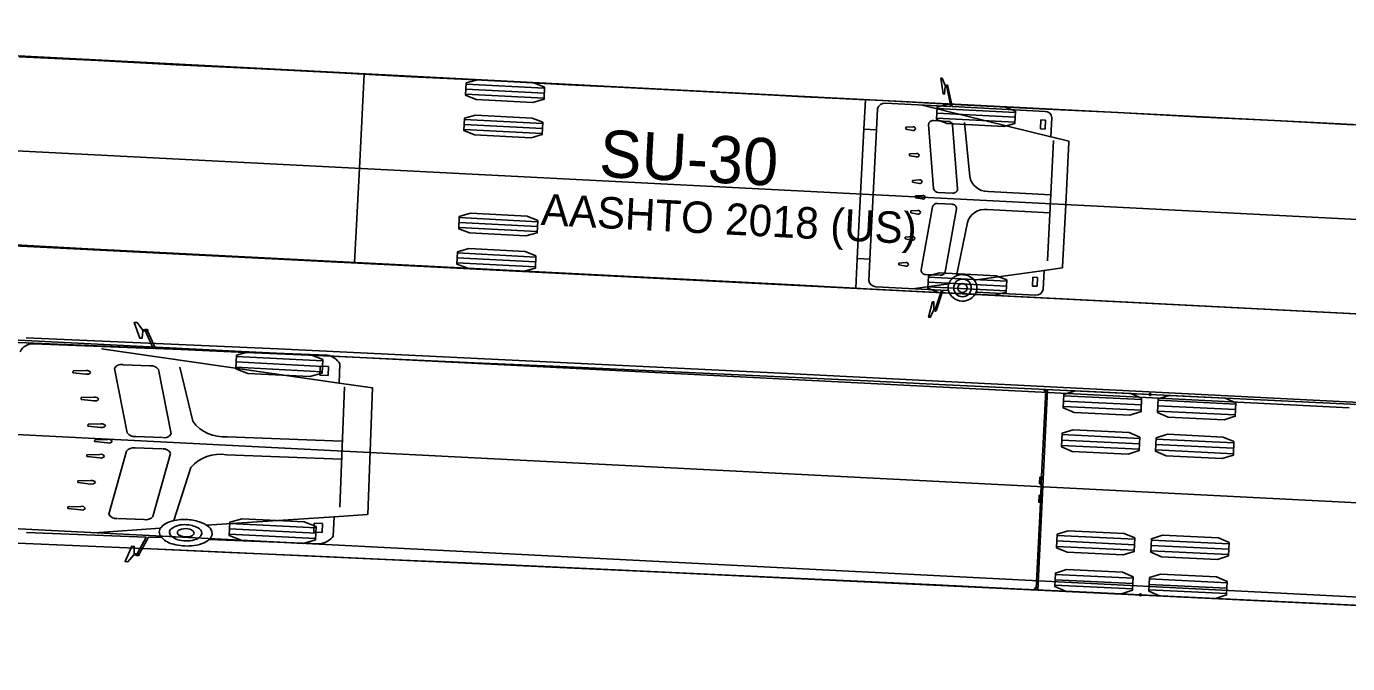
# Model space of a CAD drawing. Extents: x 260275 to 261282, y 610916 to 614143.
# Drawn here: x 261170.4 to 261226.4, y 611587.4 to 611614.4 of the extents above; entities that cross this region are included whole.
import ezdxf

# ---------------------------------------------------------------- set-up
doc = ezdxf.new("R2010")
doc.units = 0
doc.layers.add('UT_X_Water_Cells', color=7, linetype='Continuous')

msp = doc.modelspace()

# ---------------------------------------------------------------- linework, layer by layer
at = {"layer": 'UT_X_Water_Cells'}
for p, q in [((261066.343, 611614.434), (261269.731, 611604.069)), ((261192.343, 611611.399), (261189.014, 611611.569)), ((261192.354, 611611.607), (261189.025, 611611.777)), ((261192.364, 611611.815), (261189.035, 611611.986)), ((261208.376, 611611.101), (261213.842, 611609.755)), ((261212.338, 611610.79), (261209.009, 611610.96)), ((261192.288, 611610.317), (261188.959, 611610.487)), ((261208.862, 611610.441), (261209.478, 611610.409)), ((261212.317, 611610.374), (261208.988, 611610.544)), ((261212.327, 611610.582), (261208.998, 611610.752)), ((261210.399, 611608.075), (261210.171, 611610.354)), ((261213.403, 611610.088), (261213.422, 611610.467)), ((261213.422, 611610.467), (261213.616, 611610.457)), ((261213.616, 611610.457), (261213.597, 611610.078)), ((261192.266, 611609.901), (261188.937, 611610.071)), ((261192.277, 611610.109), (261188.948, 611610.279)), ((261205.631, 611604.588), (261205.913, 611610.072)), ((261206.162, 611604.56), (261206.444, 611610.045)), ((261207.687, 611610.077), (261207.691, 611610.159)), ((261207.985, 611610.026), (261207.687, 611610.077)), ((261207.691, 611610.159), (261207.992, 611610.18)), ((261208.864, 611607.561), (261208.651, 611610.27)), ((261209.672, 611610.248), (261209.885, 611607.539)), ((261213.597, 611610.078), (261213.403, 611610.088)), ((261213.696, 611604.501), (261213.957, 611609.599)), ((261207.84, 611608.95), (261207.844, 611609.033)), ((261208.151, 611608.899), (261207.84, 611608.95)), ((261207.844, 611609.033), (261208.159, 611609.053)), ((261207.965, 611607.825), (261207.969, 611607.908)), ((261208.262, 611607.774), (261207.965, 611607.825)), ((261207.969, 611607.908), (261208.27, 611607.928)), ((261208.099, 611607.169), (261208.104, 611607.252)), ((261208.397, 611607.118), (261208.099, 611607.169)), ((261208.104, 611607.252), (261208.405, 611607.272)), ((261209.674, 611607.368), (261209.058, 611607.399)), ((261213.839, 611607.299), (261211.175, 611607.436)), ((261207.898, 611606.53), (261207.902, 611606.613)), ((261208.196, 611606.479), (261207.898, 611606.53)), ((261207.902, 611606.613), (261208.204, 611606.633)), ((261208.824, 611606.783), (261208.335, 611604.111)), ((261209.649, 611606.893), (261209.033, 611606.925)), ((261209.353, 611604.028), (261209.842, 611606.701)), ((261213.8, 611606.535), (261211.135, 611606.671)), ((261192.053, 611605.739), (261188.724, 611605.91)), ((261192.063, 611605.947), (261188.734, 611606.118)), ((261192.074, 611606.155), (261188.745, 611606.326)), ((261210.299, 611606.115), (261209.836, 611603.86)), ((261207.659, 611605.424), (261207.663, 611605.506)), ((261207.956, 611605.373), (261207.659, 611605.424)), ((261207.663, 611605.506), (261207.964, 611605.527)), ((261191.997, 611604.657), (261188.668, 611604.828)), ((261191.976, 611604.241), (261188.647, 611604.412)), ((261191.986, 611604.449), (261188.657, 611604.62)), ((261207.391, 611604.319), (261207.396, 611604.402)), ((261207.689, 611604.268), (261207.391, 611604.319)), ((261207.396, 611604.402), (261207.697, 611604.422)), ((261208.527, 611603.919), (261209.143, 611603.887)), ((261211.96, 611603.425), (261208.631, 611603.595)), ((261211.971, 611603.633), (261208.642, 611603.803)), ((261210.585, 611603.677), (261213.552, 611604.092)), ((261213.081, 611603.805), (261213.061, 611603.427)), ((261213.274, 611603.795), (261213.081, 611603.805)), ((261213.255, 611603.417), (261213.274, 611603.795)), ((261207.976, 611603.312), (261209.51, 611603.526)), ((261211.95, 611603.217), (261208.621, 611603.387)), ((261210.675, 611603.173), (261213.194, 611603.044)), ((261213.061, 611603.427), (261213.255, 611603.417)), ((261175.323, 611601.556), (261175.307, 611601.577)), ((261175.321, 611601.53), (261175.323, 611601.556)), ((261173.564, 611600.762), (261183.651, 611599.312)), ((261182.955, 611600.251), (261179.293, 611600.438)), ((261172.359, 611599.749), (261172.362, 611599.831)), ((261172.907, 611599.692), (261172.359, 611599.749)), ((261172.362, 611599.831), (261172.913, 611599.846)), ((261174.655, 611597.207), (261174.114, 611599.924)), ((261174.491, 611600.092), (261175.62, 611600.049)), ((261175.985, 611599.883), (261176.526, 611597.166)), ((261177.439, 611597.694), (261176.893, 611599.98)), ((261182.931, 611599.793), (261179.269, 611599.98)), ((261182.943, 611600.022), (261179.281, 611600.209)), ((261182.828, 611599.654), (261182.842, 611600.032)), ((261182.842, 611600.032), (261183.198, 611600.019)), ((261183.198, 611600.019), (261183.183, 611599.64)), ((261183.183, 611599.64), (261182.828, 611599.654)), ((261183.675, 611594.052), (261183.87, 611599.153)), ((261184.866, 611593.741), (261185.071, 611599.107)), ((261137.985, 611598.767), (261278.274, 611591.618)), ((261172.702, 611598.618), (261172.705, 611598.7)), ((261173.275, 611598.561), (261172.702, 611598.618)), ((261172.705, 611598.7), (261173.281, 611598.715)), ((261213.288, 611590.547), (261213.697, 611599.037)), ((261217.68, 611598.386), (261214.383, 611598.545)), ((261217.691, 611598.615), (261214.394, 611598.774)), ((261221.686, 611598.423), (261218.39, 611598.581)), ((261217.669, 611598.157), (261214.372, 611598.316)), ((261221.664, 611597.965), (261218.368, 611598.124)), ((261221.675, 611598.194), (261218.379, 611598.353)), ((261172.993, 611597.489), (261172.996, 611597.571)), ((261173.541, 611597.432), (261172.993, 611597.489)), ((261172.996, 611597.571), (261173.547, 611597.586)), ((261173.277, 611596.829), (261173.28, 611596.912)), ((261173.28, 611596.912), (261173.831, 611596.927)), ((261176.149, 611596.999), (261175.019, 611597.042)), ((261183.782, 611596.852), (261178.894, 611597.039)), ((261217.6, 611596.738), (261214.304, 611596.897)), ((261217.611, 611596.967), (261214.315, 611597.126)), ((261221.607, 611596.774), (261218.31, 611596.933)), ((261173.825, 611596.772), (261173.277, 611596.829)), ((261174.625, 611596.429), (261173.878, 611593.761)), ((261176.131, 611596.524), (261175.001, 611596.567)), ((261175.747, 611593.66), (261176.494, 611596.328)), ((261217.589, 611596.509), (261214.293, 611596.668)), ((261221.584, 611596.317), (261218.288, 611596.476)), ((261221.595, 611596.546), (261218.299, 611596.704)), ((261172.944, 611596.193), (261172.947, 611596.276)), ((261173.492, 611596.136), (261172.944, 611596.193)), ((261172.947, 611596.276), (261173.498, 611596.291)), ((261183.753, 611596.087), (261178.865, 611596.274)), ((261172.57, 611595.172), (261173.121, 611595.187)), ((261177.364, 611595.732), (261176.641, 611593.482)), ((261213.435, 611595.061), (261213.448, 611595.326)), ((261172.567, 611595.09), (261172.57, 611595.172)), ((261173.115, 611595.033), (261172.567, 611595.09)), ((261213.435, 611595.055), (261213.41, 611594.532)), ((261213.422, 611594.795), (261213.493, 611594.792)), ((261172.139, 611593.988), (261172.142, 611594.07)), ((261172.142, 611594.07), (261172.693, 611594.085)), ((261213.397, 611594.265), (261213.41, 611594.53)), ((261172.687, 611593.931), (261172.139, 611593.988)), ((261174.241, 611593.566), (261175.371, 611593.523)), ((261178.025, 611593.285), (261183.434, 611593.645)), ((261173.267, 611592.968), (261176.064, 611593.154)), ((261182.661, 611592.944), (261178.999, 611593.131)), ((261182.673, 611593.173), (261179.011, 611593.36)), ((261182.588, 611593.367), (261182.573, 611592.988)), ((261182.573, 611592.988), (261182.929, 611592.975)), ((261182.943, 611593.353), (261182.588, 611593.367)), ((261182.929, 611592.975), (261182.943, 611593.353)), ((261178.136, 611592.682), (261182.833, 611592.503)), ((261182.649, 611592.716), (261178.987, 611592.902)), ((261217.383, 611592.231), (261214.087, 611592.39)), ((261217.394, 611592.46), (261214.098, 611592.619)), ((261217.405, 611592.689), (261214.109, 611592.847)), ((261221.389, 611592.267), (261218.093, 611592.426)), ((261221.4, 611592.496), (261218.104, 611592.655)), ((261174.96, 611592.043), (261174.942, 611592.023)), ((261174.959, 611592.069), (261174.96, 611592.043)), ((261221.378, 611592.038), (261218.082, 611592.197)), ((261217.303, 611590.583), (261214.007, 611590.742)), ((261217.315, 611590.812), (261214.018, 611590.97)), ((261217.326, 611591.041), (261214.029, 611591.199)), ((261221.31, 611590.619), (261218.014, 611590.778)), ((261221.321, 611590.848), (261218.025, 611591.007)), ((261221.299, 611590.39), (261218.003, 611590.549))]:
    msp.add_line(p, q, dxfattribs=at)
for points in [[(261156.1, 611613.904), (261198.699, 611611.699), (261273.93, 611607.86), (261273.523, 611599.87), (261188.635, 611604.191), (261146.014, 611606.327)], [(261170.075, 611613.172), (261173.403, 611613), (261176.732, 611612.828), (261180.06, 611612.656), (261183.388, 611612.484), (261186.716, 611612.313), (261190.045, 611612.142), (261193.373, 611611.972), (261196.702, 611611.801), (261200.031, 611611.631), (261203.359, 611611.46), (261206.688, 611611.29), (261210.016, 611611.12), (261213.345, 611610.95), (261216.674, 611610.78), (261220.002, 611610.61), (261223.331, 611610.44), (261226.66, 611610.27)], [(261170.08, 611613.152), (261173.408, 611612.983), (261176.735, 611612.813), (261180.063, 611612.644), (261183.391, 611612.474), (261186.719, 611612.304), (261190.048, 611612.135), (261193.376, 611611.965), (261196.704, 611611.796), (261200.033, 611611.626), (261203.361, 611611.456), (261206.69, 611611.287), (261210.018, 611611.117), (261213.347, 611610.947), (261216.676, 611610.778), (261220.004, 611610.608), (261223.333, 611610.439), (261226.662, 611610.269)], [(261206.49, 611610.943), (261206.444, 611610.048), (261206.44, 611610.045), (261205.914, 611610.072), (261205.913, 611610.083), (261205.977, 611611.325), (261184.718, 611612.416), (261184.513, 611608.421), (261184.308, 611604.426), (261205.567, 611603.335), (261205.631, 611604.577), (261205.632, 611604.588), (261206.159, 611604.561), (261206.162, 611604.557), (261206.116, 611603.662)], [(261209.401, 611611.93), (261209.353, 611611.933), (261209.353, 611611.933), (261209.237, 611612.234), (261209.172, 611612.238), (261209.172, 611612.235), (261209.277, 611611.573), (261209.278, 611611.57), (261209.334, 611611.567), (261209.334, 611611.569), (261209.359, 611611.886), (261209.359, 611611.886), (261209.404, 611611.883)], [(261209.423, 611611.871), (261209.423, 611611.871), (261209.601, 611611.043), (261209.588, 611611.039), (261206.818, 611611.181)], [(261213.594, 611610.834), (261209.666, 611611.035), (261209.655, 611611.043), (261209.471, 611611.885), (261209.471, 611611.886)], [(261213.51, 611603.282), (261213.551, 611604.088), (261213.556, 611604.092), (261214.334, 611604.201), (261214.339, 611604.243), (261214.474, 611606.883), (261214.61, 611609.524), (261214.61, 611609.566), (261213.847, 611609.754), (261213.842, 611609.758), (261213.884, 611610.565)], [(261169.656, 611605.164), (261172.986, 611604.994), (261176.316, 611604.824), (261179.646, 611604.655), (261182.975, 611604.485), (261186.305, 611604.315), (261189.634, 611604.146), (261192.963, 611603.976), (261196.293, 611603.806), (261199.622, 611603.637), (261202.951, 611603.467), (261206.28, 611603.297), (261209.609, 611603.128), (261212.938, 611602.958), (261216.267, 611602.788), (261219.596, 611602.619), (261222.924, 611602.449), (261226.253, 611602.279), (261229.582, 611602.11)], [(261169.66, 611605.183), (261172.99, 611605.011), (261176.319, 611604.838), (261179.648, 611604.666), (261182.977, 611604.495), (261186.306, 611604.324), (261189.635, 611604.153), (261192.964, 611603.982), (261196.293, 611603.811), (261199.622, 611603.641), (261202.95, 611603.471), (261206.279, 611603.3), (261209.608, 611603.13), (261212.937, 611602.96), (261216.266, 611602.79), (261219.595, 611602.62), (261222.923, 611602.45), (261226.252, 611602.281), (261229.581, 611602.111)], [(261206.418, 611603.392), (261209.189, 611603.249), (261209.2, 611603.244), (261208.939, 611602.439), (261208.939, 611602.439)], [(261208.986, 611602.42), (261208.986, 611602.421), (261209.254, 611603.239), (261209.267, 611603.246), (261209.494, 611603.234)], [(261208.918, 611602.429), (261208.874, 611602.43), (261208.874, 611602.431), (261208.881, 611602.748), (261208.881, 611602.751), (261208.826, 611602.754), (261208.825, 611602.751), (261208.652, 611602.103), (261208.652, 611602.1), (261208.716, 611602.097), (261208.863, 611602.384), (261208.863, 611602.385), (261208.911, 611602.383)], [(261175.439, 611601.514), (261175.439, 611601.513), (261175.767, 611600.778), (261170.689, 611600.972)], [(261175.394, 611601.573), (261175.307, 611601.577), (261175.077, 611601.881), (261174.957, 611601.885), (261175.19, 611601.214), (261175.293, 611601.21), (261175.321, 611601.53), (261175.402, 611601.526)], [(261183.138, 611600.497), (261175.866, 611600.774), (261175.526, 611601.527)], [(261170.375, 611601.234), (261181.049, 611600.761), (261202.389, 611599.731), (261261.501, 611596.733), (261261.634, 611596.472), (261282.472, 611595.409), (261282.066, 611587.42), (261261.234, 611588.48), (261261.092, 611588.243), (261197.652, 611591.285), (261176.331, 611592.251), (261165.672, 611592.71)], [(261169.365, 611601.061), (261172.701, 611600.918), (261176.036, 611600.773), (261179.372, 611600.626), (261182.707, 611600.477), (261186.042, 611600.327), (261189.377, 611600.176), (261192.712, 611600.023), (261196.047, 611599.869), (261199.381, 611599.714), (261202.715, 611599.558), (261206.049, 611599.401), (261209.383, 611599.242), (261212.717, 611599.083), (261216.051, 611598.923), (261218.051, 611598.827)], [(261169.775, 611601.152), (261173.118, 611600.981), (261176.46, 611600.811), (261179.8, 611600.641), (261183.139, 611600.471), (261186.476, 611600.301), (261189.813, 611600.131), (261193.15, 611599.961), (261196.485, 611599.791), (261199.82, 611599.621), (261203.155, 611599.451), (261206.489, 611599.281), (261209.823, 611599.111), (261213.157, 611598.942), (261216.49, 611598.772), (261219.824, 611598.602), (261223.157, 611598.432), (261226.49, 611598.262)], [(261184.866, 611593.741), (261185.071, 611599.107), (261183.651, 611599.312), (261183.682, 611600.126)], [(261213.219, 611590.573), (261213.218, 611590.55), (261261.092, 611588.243), (261261.296, 611592.488), (261261.501, 611596.733), (261213.627, 611599.04), (261213.626, 611599.018)], [(261213.625, 611598.994), (261213.625, 611598.993), (261213.45, 611595.362), (261213.448, 611595.326), (261213.378, 611595.329), (261213.377, 611595.328), (261213.365, 611595.062)], [(261213.339, 611594.535), (261213.326, 611594.269), (261213.327, 611594.268), (261213.397, 611594.265), (261213.395, 611594.229), (261213.22, 611590.598), (261213.22, 611590.597)], [(261183.403, 611592.831), (261183.434, 611593.645), (261184.854, 611593.74)], [(261169.508, 611593.156), (261172.829, 611592.987), (261176.152, 611592.817), (261179.477, 611592.648), (261182.802, 611592.478), (261186.129, 611592.309), (261189.457, 611592.139), (261192.785, 611591.969), (261196.114, 611591.8), (261199.444, 611591.63), (261202.773, 611591.46), (261206.104, 611591.291), (261209.434, 611591.121), (261212.765, 611590.951), (261216.096, 611590.781), (261219.428, 611590.612), (261222.759, 611590.442), (261226.091, 611590.272), (261229.422, 611590.102)], [(261170.384, 611592.978), (261175.462, 611592.784), (261175.079, 611592.076), (261175.078, 611592.076)], [(261169.003, 611592.569), (261172.334, 611592.426), (261175.665, 611592.281), (261178.996, 611592.134), (261182.327, 611591.986), (261185.659, 611591.836), (261188.99, 611591.685), (261192.322, 611591.532), (261195.653, 611591.378), (261198.985, 611591.223), (261202.316, 611591.067), (261205.648, 611590.91), (261208.979, 611590.752), (261212.311, 611590.593), (261215.643, 611590.433), (261217.642, 611590.337)], [(261175.041, 611592.066), (261174.959, 611592.069), (261174.956, 611592.389), (261174.853, 611592.393), (261174.57, 611591.742), (261174.69, 611591.737), (261174.942, 611592.023), (261175.029, 611592.02)], [(261175.164, 611592.056), (261175.561, 611592.78), (261176.134, 611592.758)]]:
    msp.add_lwpolyline(points, dxfattribs=at)
for points in [[(261192.367, 611611.866), (261192.34, 611611.347), (261191.866, 611611.214), (261189.469, 611611.337), (261189.011, 611611.518), (261189.038, 611612.037), (261189.512, 611612.17), (261191.909, 611612.047)], [(261212.341, 611610.842), (261212.314, 611610.323), (261211.84, 611610.19), (261209.443, 611610.312), (261208.985, 611610.492), (261209.012, 611611.012), (261209.486, 611611.144), (261211.882, 611611.022)], [(261192.29, 611610.368), (261192.264, 611609.849), (261191.789, 611609.716), (261189.393, 611609.839), (261188.935, 611610.02), (261188.961, 611610.539), (261189.435, 611610.672), (261191.832, 611610.549)], [(261192.077, 611606.207), (261192.05, 611605.688), (261191.576, 611605.555), (261189.179, 611605.678), (261188.721, 611605.859), (261188.748, 611606.378), (261189.222, 611606.51), (261191.619, 611606.387)], [(261192, 611604.709), (261191.973, 611604.19), (261191.499, 611604.057), (261189.102, 611604.18), (261188.644, 611604.361), (261188.671, 611604.88), (261189.145, 611605.012), (261191.542, 611604.889)], [(261211.974, 611603.685), (261211.947, 611603.165), (261211.473, 611603.033), (261209.076, 611603.155), (261208.618, 611603.335), (261208.645, 611603.854), (261209.119, 611603.987), (261211.515, 611603.865)], [(261182.958, 611600.308), (261182.928, 611599.737), (261182.407, 611599.591), (261179.77, 611599.725), (261179.267, 611599.923), (261179.296, 611600.494), (261179.817, 611600.64), (261182.454, 611600.506)], [(261217.693, 611598.672), (261217.666, 611598.101), (261217.196, 611597.951), (261214.823, 611598.065), (261214.37, 611598.259), (261214.397, 611598.831), (261214.867, 611598.981), (261217.24, 611598.866)], [(261221.689, 611598.479), (261221.661, 611597.908), (261221.191, 611597.758), (261218.818, 611597.872), (261218.365, 611598.067), (261218.392, 611598.638), (261218.862, 611598.788), (261221.235, 611598.674)], [(261217.614, 611597.024), (261217.586, 611596.452), (261217.117, 611596.303), (261214.743, 611596.417), (261214.29, 611596.611), (261214.318, 611597.183), (261214.787, 611597.333), (261217.161, 611597.218)], [(261221.609, 611596.831), (261221.582, 611596.26), (261221.112, 611596.11), (261218.739, 611596.224), (261218.286, 611596.419), (261218.313, 611596.99), (261218.783, 611597.14), (261221.156, 611597.026)], [(261182.676, 611593.23), (261182.647, 611592.659), (261182.125, 611592.513), (261179.488, 611592.647), (261178.985, 611592.846), (261179.014, 611593.417), (261179.535, 611593.563), (261182.172, 611593.428)], [(261217.408, 611592.745), (261217.38, 611592.174), (261216.91, 611592.024), (261214.537, 611592.139), (261214.084, 611592.333), (261214.112, 611592.904), (261214.581, 611593.054), (261216.955, 611592.94)], [(261221.403, 611592.553), (261221.376, 611591.982), (261220.906, 611591.832), (261218.533, 611591.946), (261218.079, 611592.14), (261218.107, 611592.712), (261218.577, 611592.862), (261220.95, 611592.747)], [(261217.328, 611591.097), (261217.301, 611590.526), (261216.831, 611590.376), (261214.458, 611590.49), (261214.005, 611590.685), (261214.032, 611591.256), (261214.502, 611591.406), (261216.875, 611591.292)], [(261221.324, 611590.905), (261221.296, 611590.333), (261220.826, 611590.184), (261218.453, 611590.298), (261218, 611590.492), (261218.027, 611591.064), (261218.497, 611591.214), (261220.87, 611591.099)]]:
    msp.add_lwpolyline(points, close=True, dxfattribs=at)
for centre, radius in [((261210.092, 611603.348), 0.374), ((261210.092, 611603.348), 0.193), ((261213.591, 611599.008), 0.0266), ((261218.051, 611598.827), 0.0417), ((261213.185, 611590.586), 0.0266), ((261217.642, 611590.337), 0.0417)]:
    msp.add_circle(centre, radius, dxfattribs=at)
for centre, radius, start, end in [((261209.435, 611611.907), 0.0418, 329.5542, 146.5691), ((261209.436, 611611.913), 0.0434, 222.476, 253.1488), ((261206.801, 611610.859), 0.323, 87.0623, 164.9107), ((261208.835, 611610.259), 0.184, 81.5985, 176.4697), ((261209.481, 611610.217), 0.193, 9.2047, 91.1192), ((261213.602, 611610.552), 0.282, 2.6107, 91.6901), ((261208.008, 611610.114), 0.0909, 255.3432, 349.5784), ((261208.006, 611610.09), 0.091, 4.5819, 98.7457), ((261208.16, 611608.987), 0.0909, 255.3432, 349.5784), ((261208.159, 611608.963), 0.091, 4.5819, 98.7457), ((261211.161, 611608.209), 0.773, 189.9528, 271.0369), ((261208.285, 611607.862), 0.0909, 255.3432, 349.5784), ((261208.284, 611607.838), 0.091, 4.5819, 98.7457), ((261209.054, 611607.592), 0.193, 189.1998, 271.1241), ((261209.701, 611607.55), 0.184, 261.604, 356.4642), ((261208.42, 611607.206), 0.091, 255.3789, 349.5427), ((261208.419, 611607.182), 0.091, 4.5819, 98.7457), ((261208.219, 611606.567), 0.091, 255.3789, 349.5427), ((261208.218, 611606.544), 0.0909, 4.5462, 98.7814), ((261209.01, 611606.733), 0.193, 83.0005, 164.9248), ((261209.657, 611606.709), 0.184, 357.6604, 92.5206), ((261211.042, 611605.904), 0.773, 83.0877, 164.1718), ((261207.979, 611605.461), 0.091, 255.3789, 349.5427), ((261207.978, 611605.437), 0.0909, 4.5462, 98.7814), ((261207.712, 611604.356), 0.091, 255.3789, 349.5427), ((261207.711, 611604.332), 0.0909, 4.5462, 98.7814), ((261206.435, 611603.714), 0.323, 189.2139, 267.0623), ((261208.519, 611604.103), 0.184, 177.6549, 272.5261), ((261209.166, 611604.078), 0.193, 263.0054, 344.9199), ((261210.005, 611603.353), 0.524, 139.3213, 193.1214), ((261210.082, 611603.28), 0.63, 86.4171, 138.8199), ((261210.097, 611603.28), 0.629, 39.1079, 87.7972), ((261210.179, 611603.344), 0.526, 341.0075, 39.2535), ((261210.096, 611603.416), 0.628, 196.8156, 337.3073), ((261213.231, 611603.323), 0.282, 262.4345, 351.5139), ((261208.948, 611602.402), 0.0418, 207.5554, 24.5704), ((261208.947, 611602.396), 0.0434, 100.9758, 131.6486), ((261175.458, 611601.462), 0.127, 55.7089, 119.918), ((261175.456, 611601.622), 0.11, 240.761, 260.8693), ((261175.514, 611601.548), 0.0244, 298.6811, 51.9954), ((261170.637, 611600.403), 0.571, 84.7289, 155.1204), ((261183.004, 611599.717), 0.792, 31.1246, 80.28), ((261172.956, 611599.878), 0.192, 255.2359, 322.7651), ((261172.947, 611599.657), 0.192, 32.8892, 100.3637), ((261174.407, 611599.766), 0.334, 78.9506, 151.5486), ((261175.658, 611599.647), 0.403, 35.8132, 95.2711), ((261173.299, 611598.747), 0.192, 255.2359, 322.7651), ((261173.29, 611598.526), 0.192, 32.8892, 100.3637), ((261213.591, 611599.008), 0.0363, 16.3178, 337.4804), ((261173.59, 611597.618), 0.192, 255.2359, 322.7651), ((261173.582, 611597.397), 0.192, 32.8892, 100.3637), ((261178.75, 611598.663), 1.631, 216.4893, 275.08), ((261173.865, 611596.737), 0.192, 32.8892, 100.3637), ((261174.978, 611597.439), 0.397, 215.5746, 273.7376), ((261176.232, 611597.334), 0.342, 259.4153, 329.3418), ((261173.874, 611596.958), 0.192, 255.2632, 322.7378), ((261174.93, 611596.174), 0.397, 81.8893, 140.0523), ((261176.188, 611596.183), 0.342, 26.2852, 96.2117), ((261178.597, 611594.665), 1.631, 80.5469, 139.1376), ((261173.541, 611596.322), 0.192, 255.2632, 322.7378), ((261173.532, 611596.102), 0.192, 32.8618, 100.3911), ((261173.156, 611594.998), 0.192, 32.8618, 100.3911), ((261173.164, 611595.219), 0.192, 255.2632, 322.7378), ((261213.4, 611595.06), 0.0352, 357.0285, 179.6679), ((261213.4, 611595.06), 0.0352, 177.2566, 357.8431), ((261172.728, 611593.896), 0.192, 32.8618, 100.3911), ((261213.374, 611594.534), 0.0352, 356.6389, 177.2254), ((261213.374, 611594.534), 0.0354, 181.5325, 353.718), ((261172.736, 611594.117), 0.192, 255.2632, 322.7378), ((261174.183, 611593.898), 0.334, 204.0783, 276.6763), ((261175.439, 611593.92), 0.403, 260.3558, 319.8138), ((261177.072, 611591.516), 2.012, 87.4548, 106.1377), ((261177.094, 611591.478), 2.049, 72.1945, 88.1198), ((261176.319, 611592.995), 0.301, 148.0447, 231.943), ((261176.701, 611592.672), 0.799, 103.6129, 142.8805), ((261176.654, 611592.982), 0.199, 131.6168, 232.2561), ((261177.068, 611592.398), 0.914, 84.6479, 126.7059), ((261176.907, 611592.975), 0.12, 102.7896, 248.2676), ((261177.124, 611592.526), 0.617, 80.1011, 113.2919), ((261177.134, 611592.21), 1.098, 61.0792, 88.9718), ((261177.239, 611592.864), 0.27, 18.9624, 91.7062), ((261177.286, 611593.025), 0.22, 278.8233, 340.5216), ((261177.438, 611593.066), 0.407, 279.0441, 341.8485), ((261177.558, 611592.926), 0.268, 2.8861, 66.5637), ((261177.417, 611592.399), 1.074, 49.2701, 73.5389), ((261177.882, 611592.915), 0.38, 1.1439, 51.6674), ((261176.813, 611593.385), 0.924, 222.7106, 258.9887), ((261177.105, 611593.536), 0.913, 231.1231, 271.3834), ((261177.206, 611594.607), 2.204, 255.0125, 274.6477), ((261177.163, 611593.419), 0.631, 241.6217, 284.4223), ((261177.182, 611593.856), 1.234, 267.4432, 285.0253), ((261177.258, 611594.137), 1.731, 274.1986, 289.3963), ((261177.631, 611593.194), 0.719, 286.3439, 314.6009), ((261177.934, 611592.941), 0.328, 307.9018, 356.8062), ((261182.759, 611593.291), 0.792, 275.3469, 324.5024), ((261175.101, 611592.126), 0.127, 235.7089, 299.918), ((261175.088, 611591.966), 0.11, 94.7576, 114.866), ((261175.151, 611592.036), 0.0244, 303.6315, 56.9459), ((261213.185, 611590.586), 0.0363, 17.0016, 338.1642)]:
    msp.add_arc(centre, radius, start, end, dxfattribs=at)
for centre, major_axis, start_param, end_param in [((261175.461, 611601.55), (-0.0782, 0.003), 5.756759, 7.026061), ((261175.461, 611601.55), (0.0782, -0.003), 4.442794, 5.713538), ((261175.098, 611592.037), (0.0782, -0.003), 2.398717, 3.668019), ((261175.098, 611592.037), (-0.0782, 0.003), 3.71124, 4.981984)]:
    msp.add_ellipse(centre, major_axis=major_axis, ratio=0.5, start_param=start_param, end_param=end_param, dxfattribs=at)

# ---------------------------------------------------------------- texts
for s, height, p in [('SU-30', 2, (261194.651, 611608.061)), ('AASHTO 2018 (US)', 1.33333, (261192.186, 611606.018))]:
    msp.add_text(s, height=height, rotation=357.0623, dxfattribs=at).set_placement(p)

doc.saveas('drawing.dxf')
